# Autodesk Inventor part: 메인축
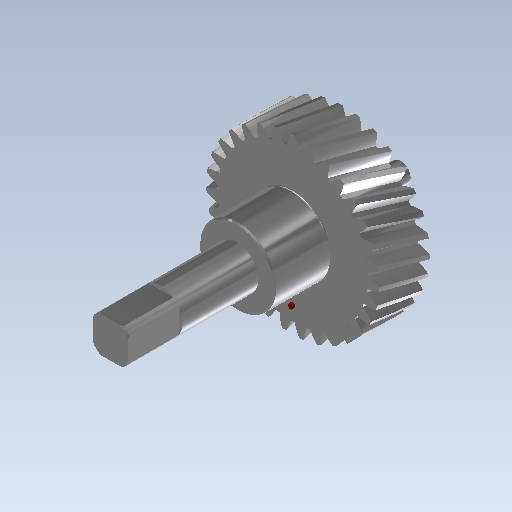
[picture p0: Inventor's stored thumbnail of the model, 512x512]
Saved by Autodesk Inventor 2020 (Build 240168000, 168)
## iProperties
CustomPartVersion: 1
Created: 2017-11
Part Number: 메인축
Material: 강철, 탄소
Document SubType Name: Modeling
Designer: mduedu
Categories: <?xml version="1.0" encoding="UTF-16"?> <MemberInstance><Categories><FamilyTemplate><FamilyTemplateParameter ValueType="xs:double" Id="1" ObjectReferenceKey="da
Density: 7.87 g/cm^3
Mass: 736.195 g
Surface Area: 200.962 cm^2
Volume: 93.5445 cm^3
Appearance: 반광택
Author: mduedu
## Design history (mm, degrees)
sketch "Sketch1"
  geometry: C1 r 34.094 at (0, 0)
  constraints: 1 centre point
  dimensions: "d0" = 68.18712 diameter of C1 (= da_da)
extrude "Extrusion1" new body sketch "Sketch1" distance "d1" = -20 (= da_b); taper "d2" = 0 deg
workplane "Work Plane2"
sketch "Sketch2"
  geometry: C1 r 34.094 at (0, 0) reference; C2 r 32.094 at (0, 0)
  constraints: 1 centre point, 1 coincident
  dimensions: "d3" = 64.18712 diameter of C2 (= da_dw)
feature "피치 지름" sketch "Sketch2" dims "d4" = 10, "d5" = 0
workplane "Work Plane8"
workplane "Work Plane9"
feature "스퍼 기어" dims "da_b" = -20, "da_d" = 64.18712, "da_aw" = 54.86964, "da_da" = 68.18712, "da_df" = 59.18712, "da_dw" = 64.18712, angle "da_beta" = 15 deg, "da_lefttooth" = 0, "da_righttooth" = 10
sketch "스케치3"
  geometry: C1 r 15 at (0, 0); 1 further point
  constraints: 1 centre point, 1 coincident
  dimensions: "d49" = 30 diameter of C1
extrude "돌출2" join sketch "스케치3" distance "d50" = 22; taper "d51" = 0 deg
sketch "스케치4"
  geometry: C1 r 8.5 at (0, 0); 1 further point
  constraints: 1 centre point, 1 coincident
  dimensions: "d52" = 17 diameter of C1
extrude "돌출3" join sketch "스케치4" distance "d53" = 50; taper "d54" = 0 deg
sketch "스케치5"
  geometry: C1 r 7.5 at (0, 0); 1 further point
  constraints: 1 centre point, 1 coincident
  dimensions: "d55" = 15 diameter of C1
extrude "돌출4" join sketch "스케치5" distance "d56" = 16; taper "d57" = 0 deg
sketch "스케치6"
  geometry: C1 r 4 at (0, 0); 1 further point
  constraints: 1 centre point, 1 coincident
  dimensions: "d58" = 8 diameter of C1
extrude "돌출5" join sketch "스케치6" distance "d59" = 7; taper "d60" = 0 deg
chamfer "모따기1" distance "d61" = 0.5; stored, may be unused: second distance "d62" = 2, angle "d63" = 45 deg
fillet "모깎기1" dims "d64" = 0.5
sketch "스케치7"
  geometry: L1 (-7, -7)-(7, -7); L2 (7, -7)-(7, 7); L3 (7, 7)-(-7, 7); L4 (-7, 7)-(-7, -7); L5 (-7, -7)-(7, 7); L6 (7, -7)-(-7, 7); L7 (-10, -10)-(10, -10); L8 (10, -10)-(10, 10); L9 (10, 10)-(-10, 10); L10 (-10, 10)-(-10, -10); L11 (-10, -10)-(10, 10); L12 (10, -10)-(-10, 10); 1 further point
  constraints: 24 end point, 4 equal length, 4 midpoint, 2 perpendicular, 1 horizontal, 1 vertical
  dimensions: "d65" = 14 distance of L3.end L2.end; "d66" = 14 distance of L2.end L1.end; "d67" = 20 distance of L9.end L8.end; "d68" = 20 distance of L8.end L7.end
extrude "돌출6" cut sketch "스케치7" distance "d69" = 20; taper "d70" = 0 deg
sketch "스케치8"
  geometry: C1 r 1 at (0, -24); 1 further point
  constraints: 1 centre point, 1 vertical alignment
  dimensions: "d71" = 2 diameter of C1; "d72" = 24 distance of point (0, 0) C1.centre
extrude "돌출7" join sketch "스케치8" distance "d73" = 1; taper "d74" = 0 deg
body "Solid1"
body "Srf1"
other parameters: "d16" = 54.86964 (= da_aw), "d17" = 0, "d34" = 1.01342 (computed from da_z), "d39" = 0, "d41" = 0, "d43" = 54.86964 (= da_aw), "d46" = 54.86964 (= da_aw), "d47" = 0, "d48" = 0
